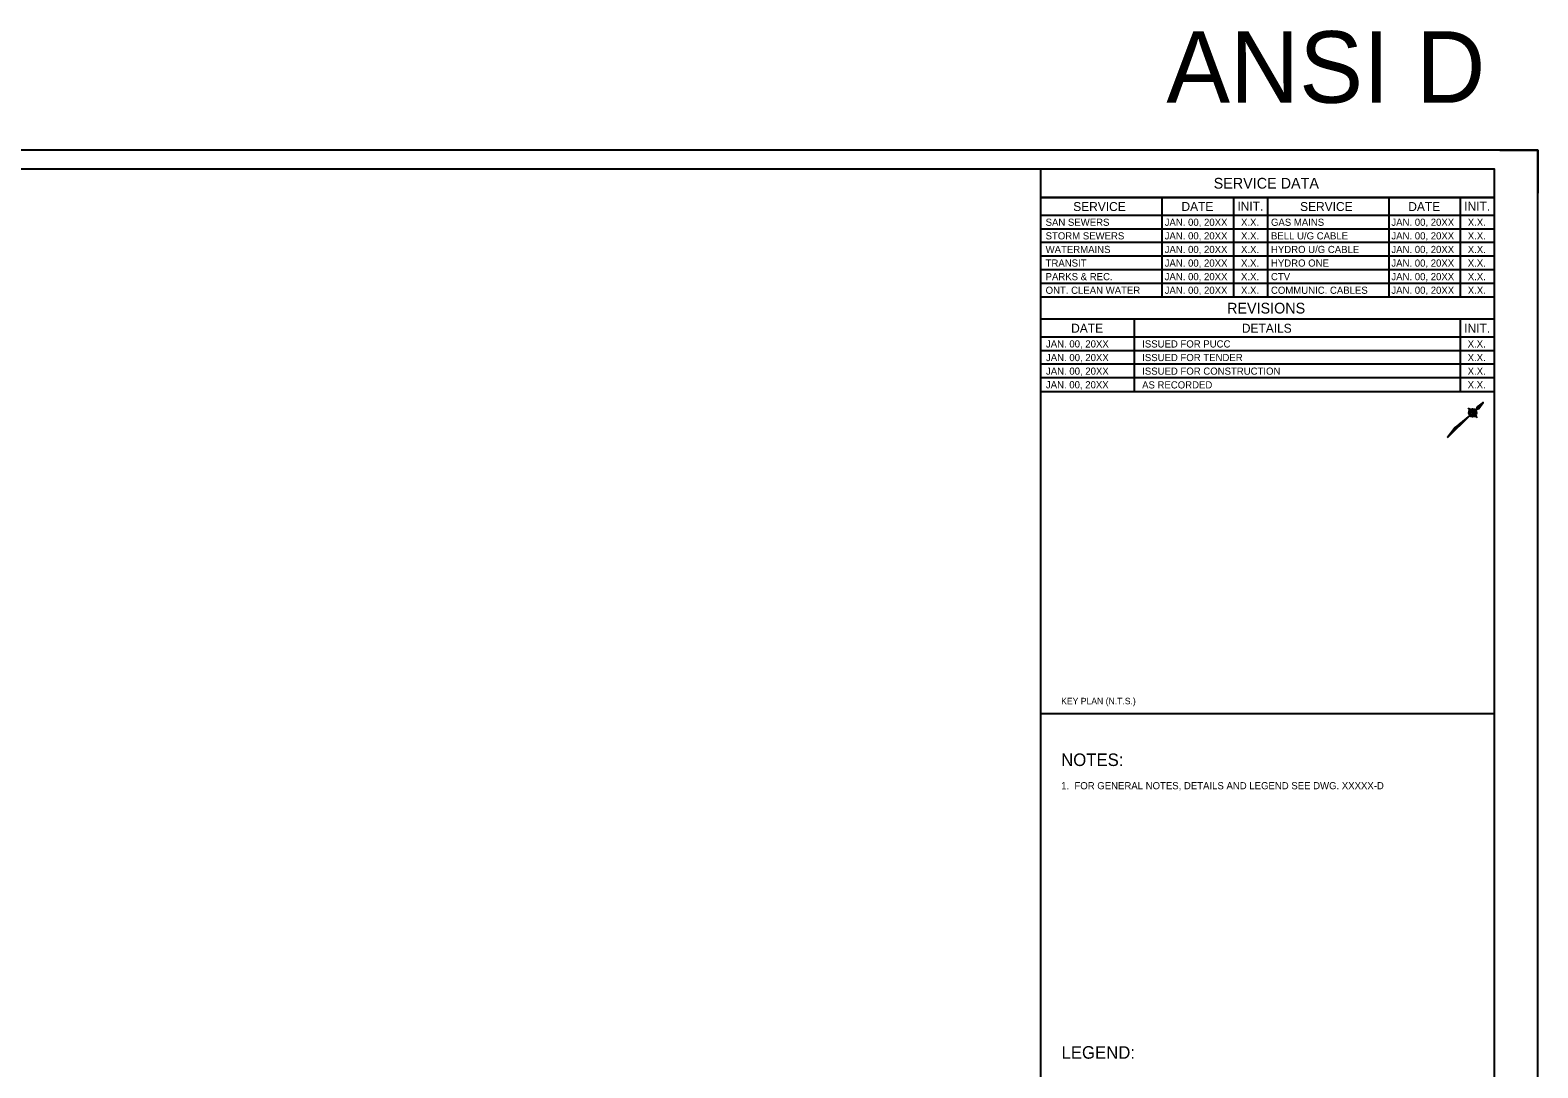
# Model space of a CAD drawing. Extents: x 613360 to 613780, y 4825621 to 4825911.
# Drawn here: x 613569.5 to 613780.3, y 4825766.5 to 4825911.5 of the extents above; entities that cross this region are included whole.
import ezdxf

# ---------------------------------------------------------------- set-up
doc = ezdxf.new("R2010")
doc.units = 0
for name, color, linetype in [('G-ANNO-KEYP', 7, 'Continuous'), ('G-ANNO-LEGN', 7, 'Continuous'), ('G-ANNO-NPLT', 7, 'Continuous'), ('G-ANNO-TEXT', 7, 'Continuous'), ('G-ANNO-TTLB-TEXT', 7, 'Continuous'), ('G-TTLB-OTLN', 7, 'Continuous'), ('G-TTLB-OTLN-PB', 7, 'Continuous')]:
    doc.layers.add(name, color=color, linetype=linetype)

msp = doc.modelspace()

# ---------------------------------------------------------------- linework, layer by layer
at = {"layer": 'G-ANNO-KEYP'}
for p, q in [((613770.76, 4825857.62), (613767.64, 4825854.56)), ((613767.74, 4825854.69), (613770.74, 4825857.6)), ((613770.76, 4825857.62), (613768.73, 4825855.97)), ((613770.77, 4825858.38), (613770.51, 4825858.64)), ((613770.56, 4825858.46), (613770.71, 4825858.31)), ((613770.68, 4825858.07), (613770.78, 4825858.17)), ((613770.68, 4825858.05), (613770.76, 4825858.13)), ((613770.68, 4825858.03), (613770.76, 4825858.11)), ((613770.68, 4825858.01), (613770.75, 4825858.08)), ((613770.68, 4825857.99), (613770.74, 4825858.06)), ((613770.68, 4825857.97), (613770.74, 4825858.04)), ((613770.68, 4825857.96), (613770.74, 4825858.02)), ((613770.68, 4825857.94), (613770.74, 4825858)), ((613770.68, 4825857.92), (613770.74, 4825857.98)), ((613770.68, 4825857.91), (613770.74, 4825857.96)), ((613770.69, 4825858.59), (613770.84, 4825858.44)), ((613770.69, 4825858.12), (613770.85, 4825858.28)), ((613770.69, 4825858.1), (613770.8, 4825858.2)), ((613770.69, 4825857.89), (613770.74, 4825857.94)), ((613770.69, 4825857.87), (613770.75, 4825857.93)), ((613770.7, 4825858.15), (613771.01, 4825858.44)), ((613770.7, 4825857.86), (613770.75, 4825857.91)), ((613770.7, 4825857.85), (613770.75, 4825857.9)), ((613770.71, 4825858.18), (613770.97, 4825858.43)), ((613770.71, 4825857.83), (613770.76, 4825857.88)), ((613770.71, 4825857.82), (613770.76, 4825857.87)), ((613770.72, 4825857.8), (613770.77, 4825857.85)), ((613770.72, 4825857.79), (613770.77, 4825857.84)), ((613770.73, 4825858.21), (613770.94, 4825858.42)), ((613770.73, 4825857.78), (613770.78, 4825857.82)), ((613770.74, 4825857.77), (613770.78, 4825857.81)), ((613770.74, 4825857.75), (613770.79, 4825857.8)), ((613770.75, 4825857.74), (613770.8, 4825857.79)), ((613770.76, 4825858.26), (613770.89, 4825858.39)), ((613770.76, 4825857.73), (613770.8, 4825857.78)), ((613770.77, 4825857.72), (613770.81, 4825857.76)), ((613770.77, 4825857.71), (613770.82, 4825857.75)), ((613770.78, 4825857.7), (613770.83, 4825857.74)), ((613770.79, 4825857.69), (613770.84, 4825857.73)), ((613770.8, 4825857.68), (613770.85, 4825857.72)), ((613770.81, 4825857.67), (613770.86, 4825857.71)), ((613770.82, 4825857.66), (613770.86, 4825857.7)), ((613770.83, 4825857.65), (613770.87, 4825857.69)), ((613770.84, 4825857.64), (613770.88, 4825857.68)), ((613770.85, 4825857.63), (613770.9, 4825857.67)), ((613770.86, 4825857.62), (613770.91, 4825857.67)), ((613770.87, 4825858.3), (613771.03, 4825858.45)), ((613770.87, 4825858.3), (613771.03, 4825858.45)), ((613770.87, 4825857.61), (613770.92, 4825857.66)), ((613770.88, 4825857.61), (613770.93, 4825857.65)), ((613771.16, 4825858.25), (613770.89, 4825857.99)), ((613770.89, 4825857.99), (613770.92, 4825857.96)), ((613770.89, 4825857.6), (613770.94, 4825857.64)), ((613770.91, 4825857.59), (613770.95, 4825857.64)), ((613770.92, 4825857.96), (613771.11, 4825858.14)), ((613770.92, 4825857.58), (613770.97, 4825857.63)), ((613770.93, 4825857.58), (613770.98, 4825857.62)), ((613770.94, 4825857.57), (613770.99, 4825857.62)), ((613770.95, 4825858.35), (613771.06, 4825858.46)), ((613770.96, 4825857.56), (613771.01, 4825857.61)), ((613770.97, 4825857.56), (613771.02, 4825857.61)), ((613770.98, 4825857.55), (613771.04, 4825857.6)), ((613770.99, 4825858.37), (613771.08, 4825858.46)), ((613771, 4825857.55), (613771.05, 4825857.6)), ((613771.01, 4825857.54), (613771.07, 4825857.6)), ((613771.02, 4825858.38), (613771.1, 4825858.46)), ((613771.03, 4825857.54), (613771.08, 4825857.59)), ((613771.04, 4825857.54), (613771.1, 4825857.59)), ((613771.05, 4825858.39), (613771.12, 4825858.46)), ((613771.06, 4825857.53), (613771.12, 4825857.59)), ((613771.07, 4825858.39), (613771.14, 4825858.47)), ((613771.08, 4825857.53), (613771.14, 4825857.59)), ((613771.09, 4825857.53), (613771.16, 4825857.59)), ((613771.1, 4825858.4), (613771.16, 4825858.46)), ((613771.11, 4825858.14), (613771.12, 4825857.75)), ((613771.11, 4825857.53), (613771.18, 4825857.59)), ((613771.12, 4825858.4), (613771.18, 4825858.46)), ((613771.12, 4825857.75), (613771.39, 4825858.02)), ((613771.13, 4825857.53), (613771.2, 4825857.59)), ((613771.14, 4825858.4), (613771.2, 4825858.46)), ((613771.15, 4825857.52), (613771.22, 4825857.6)), ((613771.16, 4825858.4), (613771.22, 4825858.46)), ((613771.17, 4825857.87), (613771.16, 4825858.25)), ((613771.36, 4825858.05), (613771.17, 4825857.87)), ((613771.17, 4825857.53), (613771.25, 4825857.6)), ((613771.18, 4825858.4), (613771.23, 4825858.46)), ((613771.19, 4825858.4), (613771.25, 4825858.45)), ((613771.19, 4825857.53), (613771.28, 4825857.61)), ((613771.21, 4825858.4), (613771.27, 4825858.45)), ((613771.21, 4825857.53), (613771.31, 4825857.62)), ((613771.23, 4825858.39), (613771.28, 4825858.45)), ((613771.24, 4825858.39), (613771.3, 4825858.44)), ((613771.24, 4825857.53), (613771.35, 4825857.64)), ((613771.26, 4825858.39), (613771.31, 4825858.44)), ((613771.26, 4825857.54), (613771.6, 4825857.86)), ((613771.27, 4825858.38), (613771.32, 4825858.43)), ((613771.29, 4825858.38), (613771.34, 4825858.42)), ((613771.29, 4825857.55), (613771.59, 4825857.84)), ((613771.3, 4825858.37), (613771.35, 4825858.42)), ((613771.31, 4825858.37), (613771.36, 4825858.41)), ((613771.32, 4825857.56), (613771.58, 4825857.81)), ((613771.32, 4825857.56), (613771.58, 4825857.81)), ((613771.33, 4825858.36), (613771.38, 4825858.41)), ((613771.34, 4825858.35), (613771.39, 4825858.4)), ((613771.35, 4825858.35), (613771.4, 4825858.39)), ((613771.36, 4825858.34), (613771.41, 4825858.38)), ((613771.39, 4825858.02), (613771.36, 4825858.05)), ((613771.36, 4825857.58), (613771.56, 4825857.77)), ((613771.38, 4825858.33), (613771.42, 4825858.38)), ((613771.39, 4825858.32), (613771.43, 4825858.37)), ((613771.4, 4825858.31), (613771.44, 4825858.36)), ((613771.41, 4825858.31), (613771.45, 4825858.35)), ((613771.41, 4825857.6), (613771.53, 4825857.72)), ((613771.42, 4825858.3), (613771.46, 4825858.34)), ((613771.43, 4825858.29), (613771.47, 4825858.33)), ((613771.44, 4825858.28), (613771.48, 4825858.32)), ((613771.45, 4825858.27), (613771.49, 4825858.31)), ((613771.6, 4825857.4), (613771.45, 4825857.55)), ((613771.46, 4825858.26), (613771.5, 4825858.3)), ((613771.47, 4825858.25), (613771.51, 4825858.29)), ((613771.47, 4825858.24), (613771.52, 4825858.28)), ((613771.48, 4825858.22), (613771.53, 4825858.27)), ((613771.49, 4825858.21), (613771.54, 4825858.26)), ((613771.49, 4825857.78), (613771.6, 4825857.89)), ((613771.5, 4825858.2), (613771.54, 4825858.25)), ((613771.5, 4825858.19), (613771.55, 4825858.23)), ((613771.51, 4825858.18), (613771.56, 4825858.22)), ((613771.51, 4825857.82), (613771.61, 4825857.91)), ((613771.52, 4825858.16), (613771.56, 4825858.21)), ((613771.52, 4825858.15), (613771.57, 4825858.2)), ((613771.53, 4825858.14), (613771.58, 4825858.18)), ((613771.53, 4825858.12), (613771.58, 4825858.17)), ((613771.53, 4825857.85), (613771.61, 4825857.94)), ((613771.53, 4825857.61), (613771.78, 4825857.35)), ((613771.54, 4825858.11), (613771.59, 4825858.16)), ((613771.54, 4825858.09), (613771.59, 4825858.14)), ((613771.54, 4825858.08), (613771.6, 4825858.13)), ((613771.54, 4825857.91), (613771.62, 4825857.98)), ((613771.54, 4825857.88), (613771.61, 4825857.96)), ((613771.55, 4825858.06), (613771.6, 4825858.11)), ((613771.55, 4825858.05), (613771.6, 4825858.1)), ((613771.55, 4825858.03), (613771.61, 4825858.08)), ((613771.55, 4825858.01), (613771.61, 4825858.07)), ((613771.55, 4825857.99), (613771.61, 4825858.05)), ((613771.55, 4825857.97), (613771.61, 4825858.03)), ((613771.55, 4825857.95), (613771.62, 4825858.01)), ((613771.55, 4825857.93), (613771.62, 4825858)), ((613771.74, 4825857.53), (613771.59, 4825857.68)), ((613772.61, 4825859.43), (613771.63, 4825858.47)), ((613771.8, 4825858.85), (613771.63, 4825858.47)), ((613772.01, 4825858.63), (613771.63, 4825858.47)), ((613771.64, 4825858.47), (613772.57, 4825859.38)), ((613771.67, 4825858.49), (613772.52, 4825859.31)), ((613771.71, 4825858.5), (613772.47, 4825859.24)), ((613771.74, 4825858.51), (613772.42, 4825859.17)), ((613771.78, 4825858.53), (613772.37, 4825859.1)), ((613772.61, 4825859.43), (613771.8, 4825858.85)), ((613771.81, 4825858.54), (613772.32, 4825859.04)), ((613771.84, 4825858.56), (613772.27, 4825858.97)), ((613771.88, 4825858.57), (613772.22, 4825858.9)), ((613771.91, 4825858.59), (613772.16, 4825858.83)), ((613771.95, 4825858.6), (613772.11, 4825858.76)), ((613771.98, 4825858.61), (613772.06, 4825858.69)), ((613772.61, 4825859.43), (613772.01, 4825858.63)), ((613768.73, 4825855.97), (613767.64, 4825854.56)), ((613767.68, 4825854.61), (613769.09, 4825855.98)), ((613767.8, 4825854.77), (613770.62, 4825857.51)), ((613767.86, 4825854.84), (613770.5, 4825857.41)), ((613767.92, 4825854.92), (613770.39, 4825857.31)), ((613767.98, 4825854.99), (613770.27, 4825857.22)), ((613768.04, 4825855.07), (613770.15, 4825857.12)), ((613768.1, 4825855.15), (613770.03, 4825857.02)), ((613768.15, 4825855.22), (613769.91, 4825856.92)), ((613768.21, 4825855.3), (613769.79, 4825856.83)), ((613768.27, 4825855.37), (613769.67, 4825856.73)), ((613768.33, 4825855.45), (613769.55, 4825856.63)), ((613768.39, 4825855.53), (613769.43, 4825856.54)), ((613768.45, 4825855.6), (613769.31, 4825856.44)), ((613768.51, 4825855.68), (613769.19, 4825856.34)), ((613768.57, 4825855.75), (613769.07, 4825856.25)), ((613768.62, 4825855.83), (613768.95, 4825856.15)), ((613768.68, 4825855.91), (613768.83, 4825856.05))]:
    msp.add_line(p, q, dxfattribs=at)
for points in [[(613767.64, 4825854.56), (613770.76, 4825857.62), (613768.73, 4825855.97)], [(613771.63, 4825858.47), (613772.01, 4825858.63), (613772.61, 4825859.43)]]:
    msp.add_lwpolyline(points, close=True, dxfattribs=at)
for radius in [0.541, 0.47, 0.407, 0.348]:
    msp.add_circle((613771.15, 4825858), radius, dxfattribs=at)
at = {"layer": 'G-TTLB-OTLN'}
for p, q in [((613710.78, 4825860.98), (613710.78, 4825892.08)), ((613774.18, 4825888.08), (613710.78, 4825888.08)), ((613710.78, 4825888.08), (613774.18, 4825888.08)), ((613727.73, 4825888.08), (613727.73, 4825874.18)), ((613737.73, 4825888.08), (613737.73, 4825874.18)), ((613742.48, 4825888.08), (613742.48, 4825874.18)), ((613759.43, 4825888.08), (613759.43, 4825874.18)), ((613769.43, 4825888.08), (613769.43, 4825874.18)), ((613774.18, 4825885.58), (613710.78, 4825885.58)), ((613774.18, 4825883.68), (613710.78, 4825883.68)), ((613774.18, 4825881.78), (613710.78, 4825881.78)), ((613774.18, 4825879.88), (613710.78, 4825879.88)), ((613774.18, 4825877.98), (613710.78, 4825877.98)), ((613774.18, 4825876.08), (613710.78, 4825876.08)), ((613774.18, 4825874.18), (613710.78, 4825874.18)), ((613774.18, 4825871.08), (613710.78, 4825871.08)), ((613723.83, 4825871.08), (613723.83, 4825860.98)), ((613769.43, 4825871.08), (613769.43, 4825860.98)), ((613774.18, 4825868.58), (613710.78, 4825868.58)), ((613774.18, 4825866.68), (613710.78, 4825866.68)), ((613774.18, 4825864.78), (613710.78, 4825864.78)), ((613774.18, 4825862.88), (613710.78, 4825862.88)), ((613710.78, 4825623.51), (613710.78, 4825815.93))]:
    msp.add_line(p, q, dxfattribs=at)
for points in [[(613380.09, 4825892.08), (613774.18, 4825892.08), (613774.18, 4825623.51), (613380.09, 4825623.51)], [(613710.78, 4825860.98), (613774.18, 4825860.98), (613774.18, 4825815.93), (613710.78, 4825815.93)]]:
    msp.add_lwpolyline(points, close=True, dxfattribs=at)
at = {"layer": 'G-TTLB-OTLN-PB'}
for p, q in [((613774.98, 4825894.68), (613780.27, 4825894.68)), ((613780.27, 4825894.68), (613780.27, 4825888.68))]:
    msp.add_line(p, q, dxfattribs=at)
msp.add_lwpolyline([(613359.58, 4825620.91), (613780.27, 4825620.91), (613780.27, 4825894.68), (613359.58, 4825894.68)], close=True, dxfattribs=at)

# ---------------------------------------------------------------- texts
at = {"layer": 'G-ANNO-KEYP'}
msp.add_text('KEY PLAN (N.T.S.)', height=0.9, rotation=359.9998, dxfattribs=at).set_placement((613713.64, 4825817.29))
at = {"layer": 'G-ANNO-LEGN'}
msp.add_text('LEGEND:', height=1.75, rotation=360, dxfattribs=at).set_placement((613713.69, 4825767.77))
at = {"layer": 'G-ANNO-NPLT'}
msp.add_text('ANSI D', height=10, dxfattribs=at).set_placement((613728.34, 4825901.32))
at = {"layer": 'G-ANNO-TEXT'}
for s, height, p in [('NOTES:', 1.75, (613713.64, 4825808.66)), ('1.  FOR GENERAL NOTES, DETAILS AND LEGEND SEE DWG. XXXXX-D', 1, (613713.64, 4825805.41))]:
    msp.add_text(s, height=height, rotation=0.0057, dxfattribs=at).set_placement(p)
at = {"layer": 'G-ANNO-TTLB-TEXT'}
for s, height, p in [('SERVICE DATA', 1.5, (613734.96, 4825889.33)), ('SERVICE', 1.25, (613715.33, 4825886.2)), ('DATE', 1.25, (613730.46, 4825886.21)), ('INIT.', 1.25, (613738.28, 4825886.24)), ('SERVICE', 1.25, (613747.04, 4825886.2)), ('DATE', 1.25, (613762.16, 4825886.2)), ('INIT.', 1.25, (613769.98, 4825886.24)), ('SAN SEWERS', 1, (613711.47, 4825884.13)), ('GAS MAINS', 1, (613742.97, 4825884.13)), ('STORM SEWERS', 1, (613711.47, 4825882.23)), ('BELL U/G CABLE', 1, (613742.97, 4825882.23)), ('WATERMAINS', 1, (613711.47, 4825880.33)), ('HYDRO U/G CABLE', 1, (613742.97, 4825880.33)), ('TRANSIT', 1, (613711.47, 4825878.43)), ('HYDRO ONE', 1, (613742.97, 4825878.43)), ('PARKS & REC.', 1, (613711.47, 4825876.53)), ('CTV', 1, (613742.97, 4825876.53)), ('ONT. CLEAN WATER ', 1, (613711.47, 4825874.63)), ('COMMUNIC. CABLES', 1, (613742.97, 4825874.63)), ('REVISIONS', 1.5, (613736.83, 4825871.88)), ('DATE', 1.25, (613715.04, 4825869.2)), ('DETAILS', 1.25, (613738.9, 4825869.2)), ('INIT.', 1.25, (613769.98, 4825869.2)), ('JAN. 00, 20XX', 1, (613711.52, 4825863.33)), ('JAN. 00, 20XX', 1, (613711.51, 4825861.43))]:
    msp.add_text(s, height=height, dxfattribs=at).set_placement(p)
for s, p in [('JAN. 00, 20XX', (613728.11, 4825884.13)), ('X.X.', (613738.78, 4825884.13)), ('JAN. 00, 20XX', (613759.8, 4825884.13)), ('X.X.', (613770.48, 4825884.13)), ('JAN. 00, 20XX', (613728.11, 4825882.23)), ('X.X.', (613738.78, 4825882.23)), ('JAN. 00, 20XX', (613759.8, 4825882.23)), ('X.X.', (613770.48, 4825882.23)), ('JAN. 00, 20XX', (613728.11, 4825880.33)), ('X.X.', (613738.78, 4825880.33)), ('JAN. 00, 20XX', (613759.8, 4825880.33)), ('X.X.', (613770.48, 4825880.33)), ('JAN. 00, 20XX', (613728.11, 4825878.43)), ('X.X.', (613738.78, 4825878.43)), ('JAN. 00, 20XX', (613759.8, 4825878.43)), ('X.X.', (613770.48, 4825878.43)), ('JAN. 00, 20XX', (613728.11, 4825876.53)), ('X.X.', (613738.78, 4825876.53)), ('JAN. 00, 20XX', (613759.8, 4825876.53)), ('X.X.', (613770.48, 4825876.53)), ('JAN. 00, 20XX', (613728.11, 4825874.63)), ('X.X.', (613738.78, 4825874.63)), ('JAN. 00, 20XX', (613759.8, 4825874.63)), ('X.X.', (613770.48, 4825874.63)), ('JAN. 00, 20XX', (613711.52, 4825867.13)), ('ISSUED FOR PUCC', (613724.97, 4825867.13)), ('X.X.', (613770.46, 4825867.13)), ('JAN. 00, 20XX', (613711.52, 4825865.23)), ('ISSUED FOR TENDER', (613724.97, 4825865.23)), ('X.X.', (613770.46, 4825865.23)), ('ISSUED FOR CONSTRUCTION', (613724.97, 4825863.33)), ('X.X.', (613770.46, 4825863.33)), ('AS RECORDED', (613724.96, 4825861.41)), ('X.X.', (613770.46, 4825861.43))]:
    msp.add_text(s, height=1, rotation=360, dxfattribs=at).set_placement(p)

doc.saveas('drawing.dxf')
